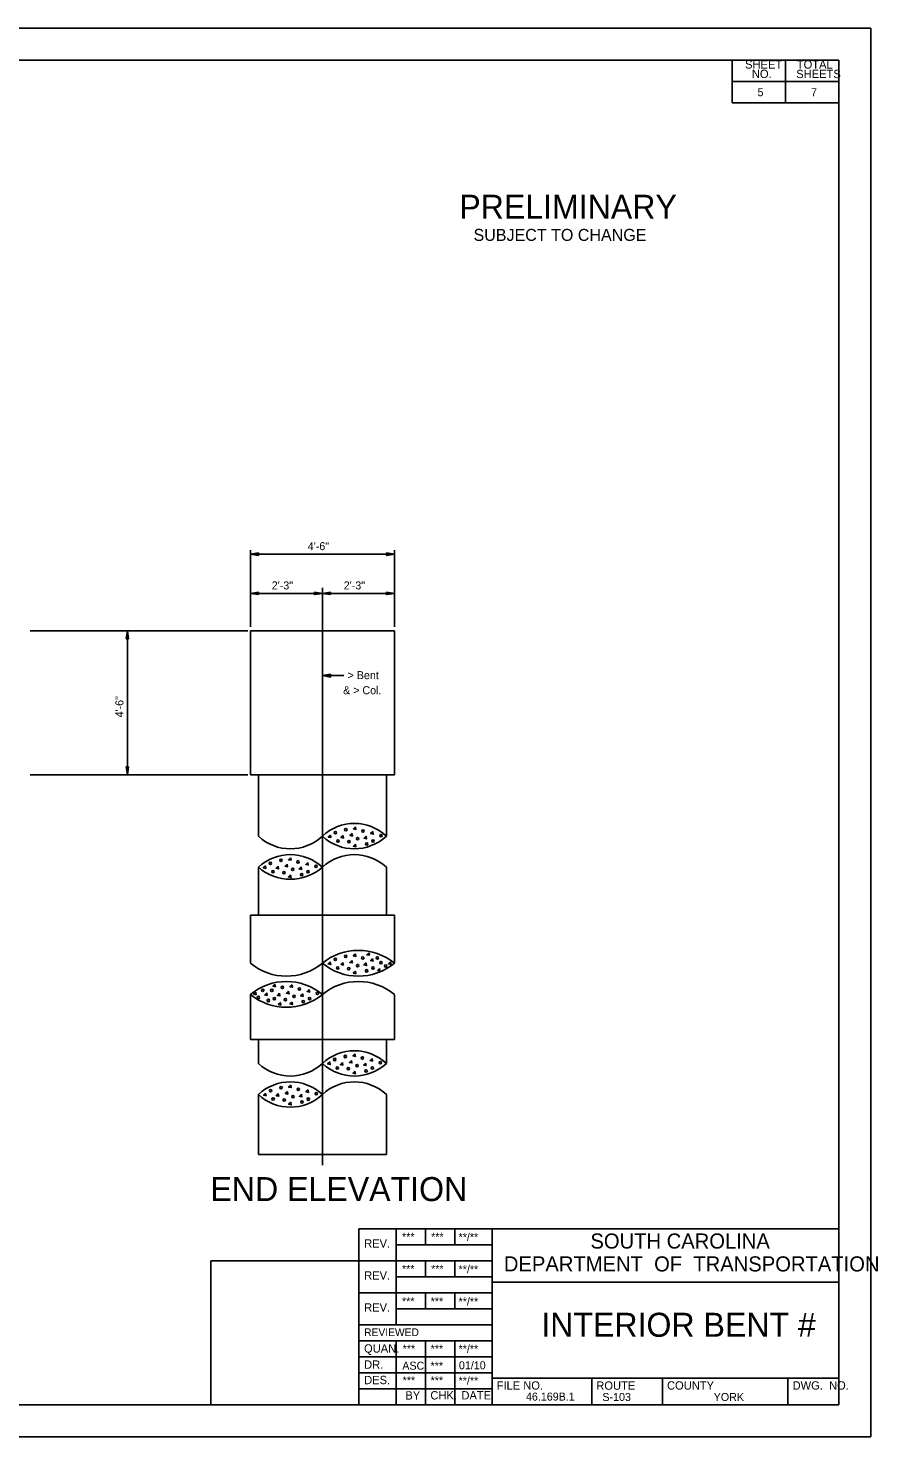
# Model space of a CAD drawing. Extents: x -437.9 to -365.7, y 404.2 to 448.2.
# Drawn here: x -392.26 to -365.71, y 404.21 to 448.22 of the extents above; entities that cross this region are included whole.
import ezdxf

# ---------------------------------------------------------------- set-up
doc = ezdxf.new("R2010")
doc.units = 0
for name, color, linetype in [('BR_AUTO DIMENSION', 7, 'Continuous'), ('BR_BORDER LINES', 7, 'Continuous'), ('BR_CENTER LINES', 7, 'Continuous'), ('BR_CONCRETE', 7, 'Continuous'), ('BR_REBAR', 7, 'Continuous'), ('BR_TEXT', 7, 'Continuous'), ('RD_SHT_IplotShp', 7, 'Continuous')]:
    doc.layers.add(name, color=color, linetype=linetype)

msp = doc.modelspace()

# ---------------------------------------------------------------- linework, layer by layer
at = {"layer": 'BR_AUTO DIMENSION'}
for p, q in [((-385.318, 429.518), (-385.318, 431.91)), ((-385.318, 431.785), (-380.818, 431.785)), ((-380.818, 429.518), (-380.818, 431.91)), ((-385.318, 429.518), (-385.318, 430.684)), ((-385.318, 430.559), (-383.068, 430.559)), ((-383.068, 430.559), (-380.818, 430.559)), ((-380.818, 429.518), (-380.818, 430.684)), ((-392.202, 429.393), (-385.402, 429.393)), ((-389.162, 429.393), (-389.162, 424.893)), ((-382.395, 427.99), (-383.068, 427.99)), ((-392.202, 424.893), (-385.402, 424.893))]:
    msp.add_line(p, q, dxfattribs=at)
for points in [[(-385.068, 431.747), (-385.318, 431.785), (-385.068, 431.822)], [(-381.068, 431.822), (-380.818, 431.785), (-381.068, 431.747)], [(-385.068, 430.521), (-385.318, 430.559), (-385.068, 430.596)], [(-383.318, 430.596), (-383.068, 430.559), (-383.318, 430.521)], [(-382.818, 430.521), (-383.068, 430.559), (-382.818, 430.596)], [(-381.068, 430.596), (-380.818, 430.559), (-381.068, 430.521)], [(-389.199, 429.143), (-389.162, 429.393), (-389.124, 429.143)], [(-382.817, 427.948), (-383.068, 427.99), (-382.817, 428.032)], [(-389.124, 425.143), (-389.162, 424.893), (-389.199, 425.143)]]:
    msp.add_lwpolyline(points, close=True, dxfattribs=at)
at = {"layer": 'BR_BORDER LINES'}
for p, q in [((-437.931, 448.216), (-365.931, 448.216)), ((-366.931, 447.213), (-434.265, 447.213)), ((-370.265, 445.88), (-370.265, 447.213)), ((-368.599, 447.213), (-368.599, 447.213)), ((-368.598, 445.88), (-368.598, 447.213)), ((-367.767, 447.213), (-367.767, 447.213)), ((-366.931, 405.213), (-366.931, 447.213)), ((-370.265, 446.554), (-366.931, 446.554)), ((-366.931, 445.88), (-370.265, 445.88)), ((-366.931, 444.885), (-366.931, 445.88)), ((-366.931, 430.787), (-366.931, 444.885)), ((-381.931, 410.713), (-366.931, 410.713)), ((-381.931, 405.213), (-381.931, 410.713)), ((-380.765, 410.713), (-380.765, 407.713)), ((-379.848, 410.213), (-379.848, 410.713)), ((-378.931, 410.213), (-378.931, 410.713)), ((-377.765, 405.213), (-377.765, 410.713)), ((-380.765, 410.213), (-377.765, 410.213)), ((-386.556, 409.713), (-381.931, 409.713)), ((-386.556, 405.213), (-386.556, 409.713)), ((-381.931, 409.713), (-377.765, 409.713)), ((-379.848, 409.213), (-379.848, 409.713)), ((-378.931, 409.213), (-378.931, 409.713)), ((-380.765, 409.213), (-377.765, 409.213)), ((-377.765, 409.046), (-366.931, 409.046)), ((-377.765, 409.046), (-377.765, 409.046)), ((-366.931, 409.046), (-366.931, 409.046)), ((-381.931, 408.713), (-377.765, 408.713)), ((-379.848, 408.213), (-379.848, 408.713)), ((-378.931, 408.213), (-378.931, 408.713)), ((-380.765, 408.213), (-377.765, 408.213)), ((-381.931, 407.713), (-377.765, 407.713)), ((-381.931, 407.213), (-377.765, 407.213)), ((-380.765, 407.213), (-380.765, 405.213)), ((-379.848, 407.213), (-379.848, 405.213)), ((-378.931, 407.213), (-378.931, 405.213)), ((-381.931, 406.713), (-377.765, 406.713)), ((-381.931, 406.213), (-377.765, 406.213)), ((-381.931, 405.713), (-377.765, 405.713)), ((-377.765, 406.046), (-366.931, 406.046)), ((-374.651, 405.213), (-374.651, 406.046)), ((-372.442, 405.213), (-372.442, 406.046)), ((-368.522, 405.213), (-368.522, 406.046)), ((-434.265, 405.213), (-366.931, 405.213))]:
    msp.add_line(p, q, dxfattribs=at)
at = {"layer": 'BR_CENTER LINES'}
msp.add_line((-383.068, 412.703), (-383.068, 430.729), dxfattribs=at)
at = {"layer": 'BR_CONCRETE'}
for p, q in [((-385.318, 429.393), (-385.318, 424.893)), ((-385.318, 429.393), (-380.818, 429.393)), ((-380.818, 429.393), (-380.818, 424.893)), ((-385.318, 424.893), (-380.818, 424.893)), ((-385.068, 424.893), (-385.068, 422.977)), ((-381.068, 424.893), (-381.068, 422.977)), ((-385.068, 422.006), (-385.068, 420.506)), ((-381.068, 422.006), (-381.068, 420.506)), ((-385.318, 420.506), (-380.818, 420.506)), ((-385.318, 420.506), (-385.318, 419.006)), ((-380.818, 420.506), (-380.818, 419.006)), ((-385.318, 416.627), (-385.318, 418.034)), ((-380.818, 416.627), (-380.818, 418.034)), ((-385.318, 416.627), (-380.818, 416.627)), ((-385.068, 416.627), (-385.068, 415.877)), ((-381.068, 416.627), (-381.068, 415.877)), ((-385.068, 414.906), (-385.068, 413.031)), ((-381.068, 414.906), (-381.068, 413.031)), ((-385.068, 413.031), (-381.068, 413.031))]:
    msp.add_line(p, q, dxfattribs=at)
for centre, radius, start, end in [((-382.068, 421.912), 1.461, 46.811, 133.189), ((-384.068, 424.042), 1.461, 226.811, 313.189), ((-382.068, 424.042), 1.461, 226.811, 313.189), ((-384.068, 420.94), 1.461, 46.811, 133.189), ((-384.068, 423.14), 1.512, 228.6075, 311.3925), ((-382.068, 420.94), 1.461, 46.811, 133.189), ((-381.943, 417.633), 1.775, 50.6575, 129.3425), ((-384.193, 420.378), 1.775, 230.6575, 309.3425), ((-381.943, 420.378), 1.775, 230.6575, 309.3425), ((-384.193, 416.662), 1.775, 50.6575, 129.3425), ((-384.193, 419.407), 1.775, 230.6575, 309.3425), ((-381.943, 416.662), 1.775, 50.6575, 129.3425), ((-382.068, 414.812), 1.461, 46.811, 133.189), ((-384.068, 416.943), 1.461, 226.811, 313.189), ((-382.068, 416.943), 1.461, 226.811, 313.189), ((-384.068, 413.841), 1.461, 46.811, 133.189), ((-382.068, 413.841), 1.461, 46.811, 133.189), ((-384.068, 415.971), 1.461, 226.811, 313.189)]:
    msp.add_arc(centre, radius, start, end, dxfattribs=at)
at = {"layer": 'BR_REBAR'}
for points in [[(-382.819, 423.011), (-382.805, 422.931), (-382.886, 422.949)], [(-382.422, 422.997), (-382.408, 422.916), (-382.489, 422.934)], [(-382.141, 423.061), (-382.127, 422.981), (-382.207, 422.999)], [(-382.032, 423.265), (-382.018, 423.185), (-382.099, 423.203)], [(-381.699, 422.979), (-381.685, 422.898), (-381.765, 422.916)], [(-381.494, 423.118), (-381.48, 423.038), (-381.561, 423.056)], [(-382.032, 422.726), (-382.018, 422.645), (-382.099, 422.663)], [(-384.847, 422.05), (-384.833, 421.97), (-384.914, 421.988)], [(-384.45, 422.035), (-384.436, 421.955), (-384.517, 421.973)], [(-384.169, 422.1), (-384.155, 422.02), (-384.235, 422.038)], [(-384.061, 422.304), (-384.047, 422.223), (-384.127, 422.242)], [(-383.727, 422.018), (-383.713, 421.937), (-383.794, 421.955)], [(-383.522, 422.157), (-383.508, 422.076), (-383.589, 422.095)], [(-384.061, 421.765), (-384.047, 421.684), (-384.127, 421.702)], [(-382.822, 419.047), (-382.808, 418.966), (-382.888, 418.984)], [(-382.425, 419.032), (-382.411, 418.951), (-382.491, 418.97)], [(-382.143, 419.097), (-382.129, 419.016), (-382.21, 419.034)], [(-382.035, 419.301), (-382.021, 419.22), (-382.102, 419.238)], [(-381.701, 419.015), (-381.687, 418.934), (-381.768, 418.952)], [(-381.613, 419.335), (-381.599, 419.254), (-381.68, 419.272)], [(-381.497, 419.154), (-381.482, 419.073), (-381.563, 419.091)], [(-380.936, 419.051), (-380.922, 418.97), (-381.003, 418.988)], [(-382.035, 418.762), (-382.021, 418.681), (-382.102, 418.699)], [(-381.278, 418.844), (-381.264, 418.763), (-381.344, 418.781)], [(-385.153, 418.103), (-385.139, 418.023), (-385.22, 418.041)], [(-384.804, 418.082), (-384.79, 418.001), (-384.871, 418.019)], [(-384.549, 418.351), (-384.535, 418.27), (-384.616, 418.288)], [(-384.407, 418.067), (-384.393, 417.986), (-384.474, 418.004)], [(-384.125, 418.132), (-384.111, 418.051), (-384.192, 418.069)], [(-384.017, 418.336), (-384.003, 418.255), (-384.084, 418.273)], [(-383.684, 418.049), (-383.67, 417.969), (-383.75, 417.987)], [(-383.479, 418.189), (-383.465, 418.108), (-383.545, 418.126)], [(-384.381, 417.78), (-384.367, 417.699), (-384.448, 417.717)], [(-384.017, 417.796), (-384.003, 417.716), (-384.084, 417.734)], [(-382.836, 415.922), (-382.822, 415.841), (-382.903, 415.86)], [(-382.439, 415.907), (-382.425, 415.826), (-382.506, 415.845)], [(-382.157, 415.972), (-382.143, 415.891), (-382.224, 415.91)], [(-382.049, 416.176), (-382.035, 416.095), (-382.116, 416.113)], [(-381.716, 415.89), (-381.702, 415.809), (-381.782, 415.827)], [(-381.511, 416.029), (-381.497, 415.948), (-381.577, 415.966)], [(-382.049, 415.637), (-382.035, 415.556), (-382.116, 415.574)], [(-384.842, 414.948), (-384.828, 414.867), (-384.908, 414.885)], [(-384.163, 414.998), (-384.149, 414.917), (-384.23, 414.935)], [(-384.055, 415.201), (-384.041, 415.121), (-384.122, 415.139)], [(-383.517, 415.054), (-383.502, 414.974), (-383.583, 414.992)], [(-384.445, 414.933), (-384.431, 414.852), (-384.511, 414.87)], [(-384.055, 414.662), (-384.041, 414.581), (-384.122, 414.6)], [(-383.721, 414.915), (-383.707, 414.834), (-383.788, 414.853)]]:
    msp.add_lwpolyline(points, close=True, dxfattribs=at)
for centre in [(-382.663, 423.089), (-382.335, 423.183), (-381.966, 422.9), (-381.801, 423.136), (-381.236, 422.993), (-382.584, 422.826), (-382.24, 422.801), (-381.683, 422.735), (-381.485, 422.825), (-384.691, 422.128), (-384.363, 422.222), (-383.83, 422.174), (-383.264, 422.032), (-384.612, 421.865), (-384.268, 421.84), (-383.994, 421.939), (-383.712, 421.774), (-383.514, 421.864), (-382.666, 419.125), (-382.337, 419.219), (-381.969, 418.935), (-381.804, 419.171), (-381.347, 419.171), (-381.238, 419.029), (-381.088, 418.921), (-382.586, 418.861), (-382.242, 418.836), (-381.686, 418.77), (-381.488, 418.861), (-384.93, 418.16), (-384.648, 418.159), (-384.319, 418.253), (-383.786, 418.206), (-383.221, 418.064), (-385.067, 417.937), (-384.756, 417.843), (-384.569, 417.896), (-384.225, 417.871), (-383.951, 417.97), (-383.668, 417.805), (-383.47, 417.896), (-382.68, 416), (-382.351, 416.094), (-381.983, 415.81), (-381.818, 416.046), (-381.253, 415.904), (-382.601, 415.736), (-382.257, 415.711), (-381.7, 415.645), (-381.502, 415.736), (-384.686, 415.025), (-384.357, 415.119), (-383.824, 415.072), (-383.258, 414.929), (-384.606, 414.762), (-384.262, 414.737), (-383.989, 414.836), (-383.706, 414.671), (-383.508, 414.761)]:
    msp.add_circle(centre, 0.0373, dxfattribs=at)
at = {"layer": 'RD_SHT_IplotShp'}
for p, q in [((-437.931, 448.213), (-365.931, 448.213)), ((-365.931, 448.213), (-365.931, 404.213)), ((-365.931, 404.213), (-437.931, 404.213))]:
    msp.add_line(p, q, dxfattribs=at)

# ---------------------------------------------------------------- texts
at = {"layer": 'BR_CONCRETE'}
for s, height, p in [('PRELIMINARY', 0.75, (-378.788, 442.262)), ('SUBJECT TO CHANGE', 0.375, (-378.344, 441.571))]:
    msp.add_text(s, height=height, dxfattribs=at).set_placement(p)
at = {"layer": 'BR_TEXT'}
for s, height, p in [('SHEET', 0.26, (-369.857, 446.953)), ('TOTAL', 0.26, (-368.239, 446.952)), ('NO.', 0.26, (-369.644, 446.658)), ('SHEETS', 0.26, (-368.257, 446.657)), ('5', 0.25, (-369.467, 446.091)), ('7', 0.25, (-367.794, 446.091)), ('4\'-6"', 0.25, (-383.525, 431.91)), ('2\'-3"', 0.25, (-384.65, 430.684)), ('2\'-3"', 0.25, (-382.4, 430.684)), ('> Bent', 0.25, (-382.28, 427.881)), ('& > Col.', 0.25, (-382.421, 427.41)), ('END ELEVATION', 0.75, (-386.566, 411.577)), ('***', 0.25, (-380.579, 410.336)), ('***', 0.25, (-379.67, 410.336)), ('**/**', 0.25, (-378.811, 410.329)), ('SOUTH CAROLINA', 0.4717, (-374.69, 410.094)), ('REV.', 0.26, (-381.762, 410.124)), ('DEPARTMENT  OF  TRANSPORTATION', 0.4717, (-377.395, 409.379)), ('REV.', 0.26, (-381.762, 409.124)), ('***', 0.25, (-380.58, 409.335)), ('***', 0.25, (-379.67, 409.335)), ('**/**', 0.25, (-378.811, 409.323)), ('REV.', 0.26, (-381.762, 408.124)), ('***', 0.25, (-380.58, 408.322)), ('***', 0.25, (-379.683, 408.322)), ('**/**', 0.25, (-378.811, 408.316)), ('INTERIOR BENT # ', 0.75, (-376.226, 407.338)), ('REVIEWED', 0.24, (-381.763, 407.36)), ('QUAN.', 0.26, (-381.765, 406.843)), ('***', 0.25, (-380.559, 406.841)), ('***', 0.25, (-379.683, 406.841)), ('**/**', 0.25, (-378.811, 406.837)), ('DR.', 0.26, (-381.764, 406.34)), ('01/10', 0.25, (-378.8, 406.323)), ('ASC', 0.25, (-380.57, 406.311)), ('***', 0.25, (-379.686, 406.311)), ('DES.', 0.26, (-381.762, 405.858)), ('***', 0.25, (-380.559, 405.853)), ('***', 0.25, (-379.686, 405.853)), ('**/**', 0.25, (-378.811, 405.844)), ('FILE NO.', 0.26, (-377.62, 405.688)), ('ROUTE', 0.26, (-374.506, 405.684)), ('COUNTY', 0.26, (-372.295, 405.688)), ('DWG.  NO.', 0.26, (-368.371, 405.688)), ('BY', 0.26, (-380.474, 405.377)), ('CHK.', 0.26, (-379.692, 405.38)), ('DATE', 0.26, (-378.722, 405.38)), ('46.169B.1', 0.25, (-376.705, 405.345)), ('S-103', 0.25, (-374.316, 405.333)), ('YORK', 0.25, (-370.837, 405.333))]:
    msp.add_text(s, height=height, dxfattribs=at).set_placement(p)
msp.add_text('4\'-6"', height=0.25, rotation=90, dxfattribs=at).set_placement((-389.287, 426.686))

doc.saveas('drawing.dxf')
